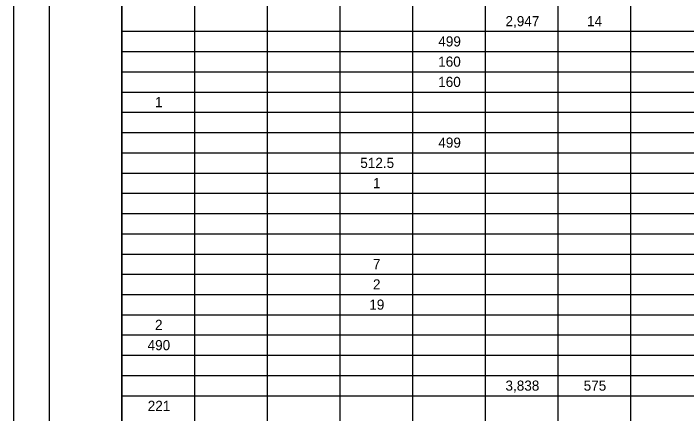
# Model space of a CAD drawing. Extents: x 0 to 34, y 0 to 22.
# Drawn here: x 0 to 9.31, y 10.89 to 16.43 of the extents above; entities that cross this region are included whole.
import ezdxf

# ---------------------------------------------------------------- set-up
doc = ezdxf.new("R2010")
doc.units = 0
for name, color, linetype in [('SH_Border', 7, 'Continuous'), ('SH_Cut_Line', 7, 'Continuous'), ('SH_Data', 7, 'Continuous'), ('SH_Text', 7, 'Continuous')]:
    doc.layers.add(name, color=color, linetype=linetype)

msp = doc.modelspace()

# ---------------------------------------------------------------- linework, layer by layer
at = {"layer": 'SH_Border'}
for points in [[(0.5, 21.5), (1.5, 21.5), (1.5, 0.5), (0.5, 0.5)], [(1.5, 21.5), (33.5, 21.5), (33.5, 0.5), (1.5, 0.5)]]:
    msp.add_lwpolyline(points, close=True, dxfattribs=at)
at = {"layer": 'SH_Cut_Line'}
msp.add_lwpolyline([(0, 0), (34, 0), (34, 22), (0, 22)], close=True, dxfattribs=at)
at = {"layer": 'SH_Data'}
for p, q in [((1.5, 21.5), (1.5, 0.5)), ((2.5047, 20.94), (2.5047, 0.5)), ((3.5094, 20.94), (3.5094, 0.5)), ((4.5141, 20.94), (4.5141, 0.5)), ((5.5188, 20.94), (5.5188, 0.5)), ((6.5235, 20.94), (6.5235, 0.5)), ((7.5282, 20.94), (7.5282, 0.5)), ((8.5329, 20.94), (8.5329, 0.5)), ((1.5, 16.18), (32.0036, 16.18)), ((1.5, 15.9), (32.0036, 15.9)), ((1.5, 15.62), (32.0036, 15.62)), ((1.5, 15.34), (32.0036, 15.34)), ((1.5, 15.06), (32.0036, 15.06)), ((1.5, 14.78), (32.0036, 14.78)), ((1.5, 14.5), (32.0036, 14.5)), ((1.5, 14.22), (32.0036, 14.22)), ((1.5, 13.94), (32.0036, 13.94)), ((1.5, 13.66), (32.0036, 13.66)), ((1.5, 13.38), (32.0036, 13.38)), ((1.5, 13.1), (32.0036, 13.1)), ((1.5, 12.82), (32.0036, 12.82)), ((1.5, 12.54), (32.0036, 12.54)), ((1.5, 12.26), (32.0036, 12.26)), ((1.5, 11.98), (32.0036, 11.98)), ((1.5, 11.7), (32.0036, 11.7)), ((1.5, 11.42), (32.0036, 11.42)), ((1.5, 11.14), (32.0036, 11.14))]:
    msp.add_line(p, q, dxfattribs=at)

# ---------------------------------------------------------------- texts
at = {"layer": 'SH_Text'}
for s, p in [('2,947', (6.8045, 16.25)), ('14', (7.9329, 16.25)), ('499', (5.8754, 15.97)), ('160', (5.8738, 15.69)), ('160', (5.8738, 15.41)), ('1', (1.9575, 15.13)), ('499', (5.8754, 14.57)), ('512.5', (4.7961, 14.29)), ('1', (4.9716, 14.01)), ('7', (4.9707, 12.89)), ('2', (4.9717, 12.61)), ('19', (4.9209, 12.33)), ('2', (1.9576, 12.05)), ('490', (1.8549, 11.77)), ('3,838', (6.8041, 11.21)), ('575', (7.8855, 11.21)), ('221', (1.8569, 10.93))]:
    msp.add_text(s, height=0.14, dxfattribs=at).set_placement(p)

doc.saveas('drawing.dxf')
